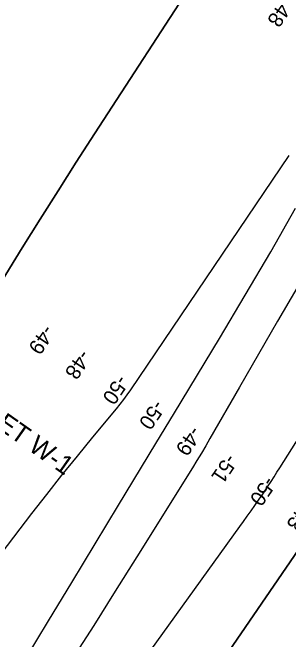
# Model space of a CAD drawing. Extents: x 3905714 to 3926767, y 183354 to 205755.
# Drawn here: x 3917028 to 3917646, y 193593 to 194998 of the extents above; entities that cross this region are included whole.
import ezdxf

# ---------------------------------------------------------------- set-up
doc = ezdxf.new("R2010")
doc.units = 0
for name, color, linetype in [('V-RIVR-JETY', 7, 'Continuous'), ('V-RIVR-RANG', 7, 'Continuous'), ('V-TOPO-DPTH', 7, 'Continuous'), ('V-TOPO-MAJR', 7, 'Continuous'), ('V-TOPO-MINR', 7, 'Continuous')]:
    doc.layers.add(name, color=color, linetype=linetype)

msp = doc.modelspace()

# ---------------------------------------------------------------- linework, layer by layer
at = {"layer": 'V-TOPO-DPTH'}
for points in [[(3916997.5, 194387.5), (3917049.2, 194470.5), (3917089.4, 194534.7), (3917129.8, 194598.7), (3917170.6, 194662.5), (3917211.5, 194726.1), (3917440.8, 195080.2)], [(3917677.2, 193807.4), (3917384.8, 193379.4)], [(3917677.2, 193807.4), (3917384.8, 193379.4)]]:
    msp.add_lwpolyline(points, dxfattribs=at)
at = {"layer": 'V-TOPO-MAJR'}
for points in [[(3917134.1, 193286.2), (3917536.7, 193845.6), (3917545.2, 193857.3), (3917553.6, 193869.1), (3917562, 193880.9), (3917570.3, 193892.8), (3917585.6, 193914.5), (3917587, 193916.5), (3917588.3, 193918.5), (3917600.3, 193936.8), (3917607, 193947), (3917613.6, 193957.2), (3917620.1, 193967.5), (3917626.6, 193977.8), (3918043.4, 194637.3), (3918058.7, 194661.1), (3918074.3, 194684.6), (3918090.3, 194707.9), (3918106.6, 194731.1), (3918360, 195084.2)], [(3918074.1, 195016.2), (3917943.2, 194842), (3917926.8, 194819.4), (3917911, 194796.5), (3917895.9, 194773.1), (3917881.4, 194749.3), (3917707.5, 194454.2), (3917664.2, 194380.5), (3917621.2, 194306.7), (3917578.4, 194232.7), (3917535.9, 194158.5), (3917470, 194043.2), (3917460.4, 194026.7), (3917450.8, 194010.3), (3917440.9, 193994), (3917430.9, 193977.8), (3917306.2, 193777.9), (3917257.9, 193701), (3917209.5, 193624.2), (3917160.8, 193547.6), (3917111.9, 193471.1), (3917038.5, 193356.8), (3917026, 193337.6)], [(3917646.8, 194677.6), (3917291.7, 194152.1), (3917284.1, 194141.2), (3917276.3, 194130.5), (3917268.2, 194120), (3917259.9, 194109.7), (3917206.9, 194045.9), (3917172.2, 194003.6), (3917137.8, 193961), (3917104, 193918), (3917070.5, 193874.7), (3916799.2, 193519.3)], [(3917056.4, 193547.6), (3917108.5, 193634.1), (3917160.6, 193720.6), (3917212.8, 193807), (3917265.1, 193893.4), (3917348.9, 194031.7), (3917359.3, 194048.9), (3917369.7, 194066.1), (3917380.2, 194083.3), (3917390.6, 194100.5), (3917491.5, 194267.5), (3917549.2, 194364.3), (3917606, 194461.6), (3917661.6, 194559.6)]]:
    msp.add_lwpolyline(points, dxfattribs=at)
at = {"layer": 'V-TOPO-MINR'}
for points in [[(3917440.8, 195080.2), (3917211.5, 194726.1), (3917170.6, 194662.5), (3917129.8, 194598.7), (3917089.4, 194534.7), (3917049.2, 194470.5), (3916997.5, 194387.5)], [(3917384.8, 193379.4), (3917677.2, 193807.4)]]:
    msp.add_lwpolyline(points, dxfattribs=at)

# ---------------------------------------------------------------- texts
at = {"layer": 'V-RIVR-JETY'}
msp.add_text('OUTLET W-1', height=42, rotation=324.8803, dxfattribs=at).set_placement((3916867, 194154.9))
at = {"layer": 'V-RIVR-RANG'}
for s, rotation, p in [('-48', 235.3754, (3917633.5, 195034.4)), ('-49', 235.8957, (3917098.1, 194300.5)), ('-48', 235.8957, (3917179.8, 194244.7)), ('-50', 235.8957, (3917263.9, 194188.2)), ('-50', 235.8957, (3917345.5, 194132)), ('-49', 235.8957, (3917427.7, 194073.4)), ('-51', 235.8957, (3917507.7, 194011.3)), ('-50', 235.8957, (3917593.9, 193960.9)), ('-43', 235.8957, (3917676.1, 193904.4))]:
    msp.add_text(s, height=33.5, rotation=rotation, dxfattribs=at).set_placement(p)

doc.saveas('drawing.dxf')
